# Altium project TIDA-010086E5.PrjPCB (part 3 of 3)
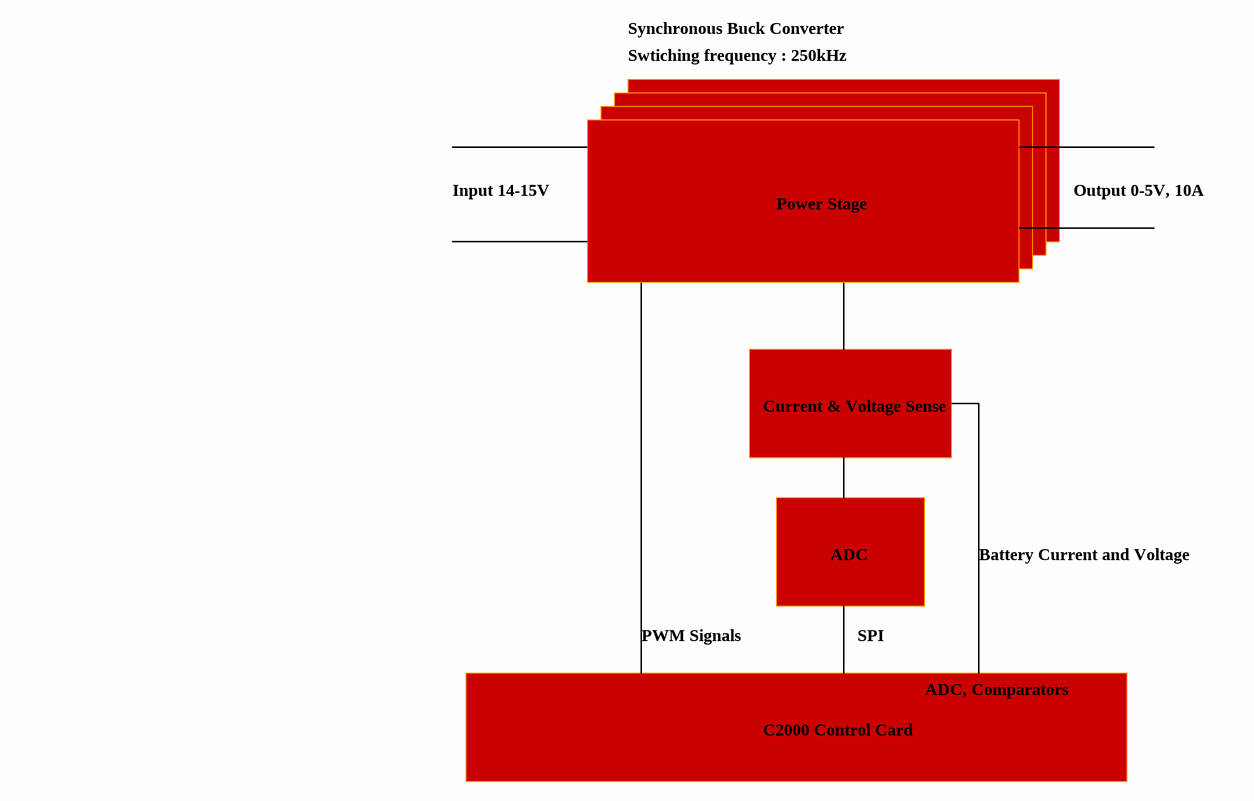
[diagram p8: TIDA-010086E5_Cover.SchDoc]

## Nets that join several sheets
1V8A: TIDA-010086E5_BiasPower (C47.1 R57.2 U9.5), TIDA-010086E5_ADC (5 pins)
3V3A: TIDA-010086E5_BiasPower (C51.1 R58.2 U11.5), TIDA-010086E5_ControlCard (C100.2 U21.8), TIDA-010086E5_ADC (C89.1 U19.4)
3V3D: TIDA-010086E5_BiasPower (5 pins), TIDA-010086E5_ControlCard (C106.2 U22.1), TIDA-010086E5_ADC (18 pins)
5VA: 1 (Q8_1.2 R14_1.2 R15_1.2), 2 (Q8_2.2 R14_2.2 R15_2.2), 3 (Q8_3.2 R14_3.2 R15_3.2), 4 (Q8_4.2 R14_4.2 R15_4.2), TIDA-010086E5_BiasPower (12 pins), TIDA-010086E5_ControlCard (C92.2 U20.4), Sns1 (C30_1.2 U4_1.6), Sns2 (C30_2.2 U4_2.6), Sns3 (C30_3.2 U4_3.6), Sns4 (C30_4.2 U4_4.6), TIDA-010086E5_ADC (18 pins)
5VD: TIDA-010086E5_BiasPower (7 pins), TIDA-010086E5_ControlCard (10 pins)
10V: 1 (5 pins), 2 (5 pins), 3 (5 pins), 4 (5 pins), TIDA-010086E5_BiasPower (J10.2 L3.1)
10VA: 1 (C23_1.1 R28_1.2 U2_1.8), 2 (C23_2.1 R28_2.2 U2_2.8), 3 (C23_3.1 R28_3.2 U2_3.8), 4 (C23_4.1 R28_4.2 U2_4.8), TIDA-010086E5_BiasPower (7 pins), Sns1 (6 pins), Sns2 (6 pins), Sns3 (6 pins), Sns4 (6 pins)
-5VA: 1 (C25_1.1 R20_1.2 U2_1.4), 2 (C25_2.1 R20_2.2 U2_2.4), 3 (C25_3.1 R20_3.2 U2_3.4), 4 (C25_4.1 R20_4.2 U2_4.4), TIDA-010086E5_BiasPower (J12.1), Sns1 (6 pins), Sns2 (6 pins), Sns3 (6 pins), Sns4 (6 pins)
AGND: TIDA-010086E5_TopLevel (8 pins), 1 (9 pins), 2 (9 pins), 3 (9 pins), 4 (9 pins), TIDA-010086E5_BiasPower (31 pins), TIDA-010086E5_ControlCard (40 pins), Sns1 (17 pins), Sns2 (17 pins), Sns3 (17 pins), Sns4 (17 pins), TIDA-010086E5_ADC (65 pins)
PGND: TIDA-010086E5_TopLevel (C1.2 C2.2 J2.1 T2.1), 1 (36 pins), 2 (36 pins), 3 (36 pins), 4 (36 pins), TIDA-010086E5_BiasPower (11 pins)
REF1V25: Sns1 (R44_1.2 U4_1.5), Sns2 (R44_2.2 U4_2.5), Sns3 (R44_3.2 U4_3.5), Sns4 (R44_4.2 U4_4.5), TIDA-010086E5_ADC (U19.8 U19.9)
REF2V5_C2K: TIDA-010086E5_ControlCard (R123.1 R129.2), TIDA-010086E5_ADC (C91.1 R115.2)
BATSN1: 1 (J8_1.2 R9_1.2), Sns1 (R39_1.2 U4_1.3 U6_1.1)
BATSN2: 2 (J8_2.2 R9_2.2), Sns2 (R39_2.2 U4_2.3 U6_2.1)
BATSN3: 3 (J8_3.2 R9_3.2), Sns3 (R39_3.2 U4_3.3 U6_3.1)
BATSN4: 4 (J8_4.2 R9_4.2), Sns4 (R39_4.2 U4_4.3 U6_4.1)
BATSP1: 1 (J8_1.1 R6_1.2 R16_1.2), Sns1 (R32_1.2 U4_1.1 U6_1.4)
BATSP2: 2 (J8_2.1 R6_2.2 R16_2.2), Sns2 (R32_2.2 U4_2.1 U6_2.4)
BATSP3: 3 (J8_3.1 R6_3.2 R16_3.2), Sns3 (R32_3.2 U4_3.1 U6_3.4)
BATSP4: 4 (J8_4.1 R6_4.2 R16_4.2), Sns4 (R32_4.2 U4_4.1 U6_4.4)
CAN_GND: TIDA-010086E5_TopLevel (J16.2), TIDA-010086E5_ControlCard (C105.1 U22.9 U22.10 U22.15)
CAN_VCC: TIDA-010086E5_TopLevel (J16.1), TIDA-010086E5_ControlCard (C105.2 U22.16)
CANH: TIDA-010086E5_TopLevel (J15.1), TIDA-010086E5_ControlCard (R164.2 U22.13)
CANL: TIDA-010086E5_TopLevel (J15.2), TIDA-010086E5_ControlCard (R164.1 U22.12)
CONVST: TIDA-010086E5_ControlCard (R135.2), TIDA-010086E5_ADC (R76.2 U16.68)
CSn_DAC: TIDA-010086E5_ControlCard (R149.2), TIDA-010086E5_ADC (U17.12)
CSnA: TIDA-010086E5_ControlCard (R148.1 R154.1), TIDA-010086E5_ADC (R68.2 R70.1 TP10.1 U16.63)
EN_RLY1: 1 (R26_1.2 U2_1.5), TIDA-010086E5_ControlCard (R160.1)
EN_RLY2: 2 (R26_2.2 U2_2.5), TIDA-010086E5_ControlCard (R161.1)
EN_RLY3: 3 (R26_3.2 U2_3.5), TIDA-010086E5_ControlCard (R162.1)
EN_RLY4: 4 (R26_4.2 U2_4.5), TIDA-010086E5_ControlCard (R163.1)
EXTSYNCOUT: TIDA-010086E5_TopLevel (J3.1), TIDA-010086E5_ControlCard (R140.2)
ILN1: 1 (11 pins), TIDA-010086E5_ADC (R165.1)
ILN2: 2 (11 pins), TIDA-010086E5_ADC (R169.1)
ILN3: 3 (11 pins), TIDA-010086E5_ADC (R173.1)
ILN4: 4 (11 pins), TIDA-010086E5_ADC (R177.1)
ILP1: 1 (C108_1.1 R42_1.1), TIDA-010086E5_ADC (R43.1)
ILP2: 2 (C108_2.1 R42_2.1), TIDA-010086E5_ADC (R167.1)
ILP3: 3 (C108_3.1 R42_3.1), TIDA-010086E5_ADC (R171.1)
ILP4: 4 (C108_4.1 R42_4.1), TIDA-010086E5_ADC (R175.1)
IOCP1: TIDA-010086E5_ControlCard (R124.2), Sns1 (C35_1.1 R51_1.1 U7_1.1)
IOCP2: TIDA-010086E5_ControlCard (R127.2), Sns2 (C35_2.1 R51_2.1 U7_2.1)
IOCP3: TIDA-010086E5_ControlCard (R126.2), Sns3 (C35_3.1 R51_3.1 U7_3.1)
IOCP4: TIDA-010086E5_ControlCard (R128.2), Sns4 (C35_4.1 R51_4.1 U7_4.1)
IoutN1: Sns1 (R40_1.2 R41_1.2), TIDA-010086E5_ADC (U15.58 U16.74)
IoutN2: Sns2 (R40_2.2 R41_2.2), TIDA-010086E5_ADC (U15.60 U16.76)
IoutN3: Sns3 (R40_3.2 R41_3.2), TIDA-010086E5_ADC (U15.62 U16.78)
IoutN4: Sns4 (R40_4.2 R41_4.2), TIDA-010086E5_ADC (U15.64 U16.80)
IoutP1: Sns1 (R33_1.2 R36_1.2 R46_1.1 U5_1.7), TIDA-010086E5_ADC (U15.57 U16.73)
IoutP2: Sns2 (R33_2.2 R36_2.2 R46_2.1 U5_2.7), TIDA-010086E5_ADC (U15.59 U16.75)
IoutP3: Sns3 (R33_3.2 R36_3.2 R46_3.1 U5_3.7), TIDA-010086E5_ADC (U15.61 U16.77)
IoutP4: Sns4 (R33_4.2 R36_4.2 R46_4.1 U5_4.7), TIDA-010086E5_ADC (U15.63 U16.79)
ISENA1: 1 (C107_1.1 R4_1.1 R12_1.2), Sns1 (R37_1.1)
ISENA2: 2 (C107_2.1 R4_2.1 R12_2.2), Sns2 (R37_2.1)
ISENA3: 3 (C107_3.1 R4_3.1 R12_3.2), Sns3 (R37_3.1)
ISENA4: 4 (C107_4.1 R4_4.1 R12_4.2), Sns4 (R37_4.1)
ISENB1: 1 (C107_1.2 R5_1.1 R13_1.2), Sns1 (R34_1.1)
ISENB2: 2 (C107_2.2 R5_2.1 R13_2.2), Sns2 (R34_2.1)
ISENB3: 3 (C107_3.2 R5_3.1 R13_3.2), Sns3 (R34_3.1)
ISENB4: 4 (C107_4.2 R5_4.1 R13_4.2), Sns4 (R34_4.1)
LOCSEN_N1: 1 (R11_1.2), Sns1 (R50_1.2), TIDA-010086E5_ADC (R88.1)
LOCSEN_N2: 2 (R11_2.2), Sns2 (R50_2.2), TIDA-010086E5_ADC (R94.1)
LOCSEN_N3: 3 (R11_3.2), Sns3 (R50_3.2), TIDA-010086E5_ADC (R96.1)
LOCSEN_N4: 4 (R11_4.2), Sns4 (R50_4.2), TIDA-010086E5_ADC (R99.1)
LOCSEN_P1: 1 (10 pins), Sns1 (R47_1.2), TIDA-010086E5_ADC (R87.1)
LOCSEN_P2: 2 (10 pins), Sns2 (R47_2.2), TIDA-010086E5_ADC (R89.1)
LOCSEN_P3: 3 (10 pins), Sns3 (R47_3.2), TIDA-010086E5_ADC (R95.1)
LOCSEN_P4: 4 (10 pins), Sns4 (R47_4.2), TIDA-010086E5_ADC (R97.1)
MCU_INT: TIDA-010086E5_ControlCard (R158.1), TIDA-010086E5_ADC (R74.2 U16.67)
PWM_HO1: 1 (R24_1.2 U3_1.7), TIDA-010086E5_ControlCard (R130.1)
PWM_HO2: 2 (R24_2.2 U3_2.7), TIDA-010086E5_ControlCard (R134.1)
PWM_HO3: 3 (R24_3.2 U3_3.7), TIDA-010086E5_ControlCard (R131.2)
PWM_HO4: 4 (R24_4.2 U3_4.7), TIDA-010086E5_ControlCard (R139.2)
PWM_LO1: 1 (R23_1.2 U3_1.8), TIDA-010086E5_ControlCard (R132.1)
PWM_LO2: 2 (R23_2.2 U3_2.8), TIDA-010086E5_ControlCard (R136.1)
PWM_LO3: 3 (R23_3.2 U3_3.8), TIDA-010086E5_ControlCard (R133.2)
PWM_LO4: 4 (R23_4.2 U3_4.8), TIDA-010086E5_ControlCard (R138.2)
RSTn: TIDA-010086E5_ControlCard (R159.1), TIDA-010086E5_ADC (R78.2 U16.36)
SCLK_DAC: TIDA-010086E5_ControlCard (R147.2), TIDA-010086E5_ADC (U17.13)
SCLKA: TIDA-010086E5_ControlCard (R146.1 R152.1), TIDA-010086E5_ADC (R65.2 TP7.1 U16.62)
SDI_DAC: TIDA-010086E5_ControlCard (R142.2), TIDA-010086E5_ADC (U17.14)
SDIA: TIDA-010086E5_ControlCard (R141.1), TIDA-010086E5_ADC (R66.2 R77.1 TP8.1 U16.55)
SDO_DAC: TIDA-010086E5_ControlCard (R145.2), TIDA-010086E5_ADC (U17.15)
SDOA: TIDA-010086E5_ControlCard (R144.1), TIDA-010086E5_ADC (R67.2 R179.2 TP9.1 U16.57)
SDOB: TIDA-010086E5_ControlCard (R150.1), TIDA-010086E5_ADC (R73.2 U16.56)
SYNCIN: TIDA-010086E5_TopLevel (J4.1), TIDA-010086E5_ControlCard (R137.2)
V_HV: TIDA-010086E5_TopLevel (C1.1 C2.1 J1.1 T1.1), 1 (F1_1.2), 2 (F1_2.2), 3 (F1_3.2), 4 (F1_4.2), TIDA-010086E5_BiasPower (J11.3), TIDA-010086E5_ControlCard (R157.2)
VbatN1: Sns1 (R35_1.2 R39_1.1), TIDA-010086E5_ADC (U15.10 U16.11)
VbatN2: Sns2 (R35_2.2 R39_2.1), TIDA-010086E5_ADC (U15.12 U16.13)
VbatN3: Sns3 (R35_3.2 R39_3.1), TIDA-010086E5_ADC (U15.14 U16.18)
VbatN4: Sns4 (R35_4.2 R39_4.1), TIDA-010086E5_ADC (U15.16 U16.20)
VbatP1: Sns1 (R32_1.1 U4_1.4), TIDA-010086E5_ADC (U15.9 U16.12)
VbatP2: Sns2 (R32_2.1 U4_2.4), TIDA-010086E5_ADC (U15.11 U16.14)
VbatP3: Sns3 (R32_3.1 U4_3.4), TIDA-010086E5_ADC (U15.13 U16.17)
VbatP4: Sns4 (R32_4.1 U4_4.4), TIDA-010086E5_ADC (U15.15 U16.19)
VoutP1: TIDA-010086E5_ControlCard (R118.1), Sns1 (C37_1.1 R52_1.2 U7_1.7)
VoutP2: TIDA-010086E5_ControlCard (R119.1), Sns2 (C37_2.1 R52_2.2 U7_2.7)
VoutP3: TIDA-010086E5_ControlCard (R120.1), Sns3 (C37_3.1 R52_3.2 U7_3.7)
VoutP4: TIDA-010086E5_ControlCard (R121.1), Sns4 (C37_4.1 R52_4.2 U7_4.7)

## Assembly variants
ADS93x8V8I: not fitted C9_1 C9_2 C9_3 C9_4 C10_1 C10_2 C10_3 C10_4 C19_1 C19_2 C19_3 C19_4 C29_1 C29_2 C29_3 C29_4 C30_1 C30_2 C30_3 C30_4 C33_1 C33_2 C33_3 C33_4 C77 C80 C81 C105 C106 J15 J16 LBL1 R3_1 R3_2 R3_3 R3_4 R21_1 R21_2 R21_3 R21_4 R31_1 R31_2 R31_3 R31_4 R35_1 R35_2 R35_3 R35_4 R36_1 R36_1 R36_2 R36_2 R36_3 R36_3 R36_4 R36_4 R38_1 R38_2 R38_3 R38_4 R40_1 R40_2 R40_3 R40_4 R43 R61 R62 R69 R71 R75 R77 R79 R80 R81 R82 R83 R84 R85 R86 R91 R92 R98 R151 R164 R165 R167 R169 R171 R173 R175 R177 R179 U4_1 U4_2 U4_3 U4_4 U5_1 U5_2 U5_3 U5_4 U16 U22
ADS93x4: not fitted C9_1 C9_2 C9_3 C9_4 C10_1 C10_2 C10_3 C10_4 C19_1 C19_2 C19_3 C19_4 C30_1 C30_2 C30_3 C30_4 C77 C80 C81 C105 C106 LBL1 R3_1 R3_2 R3_3 R3_4 R21_1 R21_2 R21_3 R21_4 R31_1 R31_2 R31_3 R31_4 R33_1 R33_2 R33_3 R33_4 R35_1 R35_2 R35_3 R35_4 R41_1 R41_2 R41_3 R41_4 R61 R62 R69 R71 R75 R77 R79 R80 R81 R82 R83 R84 R85 R86 R91 R92 R98 R164 R179 U4_1 U4_2 U4_3 U4_4 U16 U22
ADS8686S: not fitted C9_1 C9_2 C9_3 C9_4 C10_1 C10_2 C10_3 C10_4 C19_1 C19_2 C19_3 C19_4 C64 C65 C66 C78 C79 C105 C106 LBL1 R3_1 R3_2 R3_3 R3_4 R21_1 R21_2 R21_3 R21_4 R31_1 R31_2 R31_3 R31_4 R32_1 R32_2 R32_3 R32_4 R33_1 R33_2 R33_3 R33_4 R39_1 R39_2 R39_3 R39_4 R41_1 R41_2 R41_3 R41_4 R61 R62 R65 R66 R67 R68 R70 R73 R74 R76 R78 R90 R93 R164 R179 U15 U22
